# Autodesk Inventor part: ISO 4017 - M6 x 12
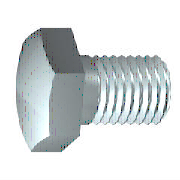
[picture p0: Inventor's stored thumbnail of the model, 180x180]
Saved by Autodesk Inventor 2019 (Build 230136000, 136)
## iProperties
Created: 2018-01
Part Number: ISO 4017 - M6 x 12
Material: Acier inoxydable 440C
Description: Vis à tête hexagonale
Document SubType Name: Modeling
Standard: ISO 4017
Designer: Thier
Standard Revision: Fourth edition 2011-04-01
Standards Organization: ISO
Language: fr-FR
Size Designation: M6 x 12
Categories: <MemberInstance><Categories><Category DisplayName="Visserie" InternalName="e4da775c-781d-43d5-af7c-5136215cf5a6" Mnemonic="FSTN"><Category DisplayName="Vis" Int
Density: 7.75 g/cm^3
Appearance: Semi-poli
IsCustomPart: 0
Author: Thier
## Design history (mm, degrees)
sketch "Esquisse1"
  geometry: L1 (0, 4.44)-(0, 3); L2 (3, 3)-(12, 3); L3 (12, 3)-(12, 0); L4 (12, 0)-(-0.5, 0); L5 (-3, 0)-(14.5, 0) reference; L6 (-0.5, 0)-(-0.5, 4.44); L7 (-0.5, 4.44)-(0, 4.44); L8 (3, 3)-(2.386, 3); L9 (2.386, 3)-(0, 3); L10 (0, -0.888)-(0, 5.328) reference
  constraints: 16 end point, 2 collinear, 2 perpendicular, 1 parallel
  dimensions: "d0" = 12 distance between parallel lines of L3 L1 (= NLG); "d1" = 9 distance from line of L2.start L3 (= GEL); "d2" = 6 diameter of L2 L4 (= GD); "d9" = 0.5001 distance between parallel lines of L6 L1 (computed from SD); "d10" = 8.88 diameter of L7 L4 (= SD2); "d13" = 0.61355 distance of L2.start L8.end (computed from GAL); "d14" = 6 diameter of L9 L4 (= BDM)
revolve "Corps" sketch "Esquisse1" stored, may be unused: angle "d12" = 90 deg
sketch "Esquisse2"
  geometry: L1 (0, 5.774)-(5, 2.887); L2 (5, 2.887)-(5, -2.887); L3 (5, -2.887)-(0, -5.774); L4 (0, -5.774)-(-5, -2.887); L5 (-5, -2.887)-(-5, 2.887); L6 (-5, 2.887)-(0, 5.774); 2 further points
  constraints: 12 end point, 1 coincident, 1 vertical, 11 other
  dimensions: "d11" = 10 distance between parallel lines of L5 L2 (= SW)
extrude "Tête" join sketch "Esquisse2" distance "d3" = 3.5 (= KOH - SD); taper "d4" = 0 deg
sketch "Esquisse4"
  geometry: L1 (-4, 5)-(-4, 5.774); L2 (-4, 5.774)-(-3.554, 5.774); L3 (-3.554, 5.774)-(-4, 5); L4 (-4.7, 0)-(0.2, 0) reference; L5 (-0.5, 5.774)-(-4, 5.774) reference; L6 (-4, 2.887)-(-4, 5.774) reference
  constraints: 6 end point, 2 collinear, 1 perpendicular, 1 vertical
  dimensions: "d5" = 30 deg angle of L3 L1 (= ANG1); "d19" = 10 diameter of L1.start L4 (= SW0)
revolve "Chanfrein1" sketch "Esquisse4" stored, may be unused: angle "d21" = 90 deg
workplane "Work Plane1"
body "Solid1"
feature "Filetage" dims "d15" = 9 (= GEL), "d16" = 0
chamfer "Chanfrein2" distance "d6" = 0.61345 (= -0.5 x SPD + 0.5 x GD); stored, may be unused: second distance "d7" = 0.61355 (computed from GUL), angle "d55" = 45 deg
other parameters: "NLG" = 12 [user parameter; used in 1 equation term], "GD" = 6 (= NND) [user parameter; used in 2 equation terms], "BDM" = 6 (= NND) [user parameter; used in 1 equation term], "KOH" = 4 [user parameter; used in 1 equation term], "GEL" = 9 [user parameter; used in 2 equation terms], "SW" = 10 [user parameter; used in 2 equation terms], "SW0" = 10 (= SW) [user parameter; used in 1 equation term], "SPD" = 4.7731 (= NND - 1.2269 x PTC) [user parameter; used in 1 equation term], "SD2" = 8.88 [user parameter; used in 2 equation terms], "SD" = 0.5 [user parameter; used in 2 equation terms], "ANG1" = 30 deg [user parameter; used in 1 equation term], "GAL" = 0.61345 (= 0.61345 x PTC) [user parameter; used in 1 equation term], "GUL" = 0.61345 (= 0.61345 x PTC) [user parameter; used in 1 equation term], "d8" = 0, "RR" = 0.25 [user parameter], "d57" = 0, "d58" = 0, "GD1" = 4.7731 (= THREADDIA - 1.2269 x PTC) [user parameter], "THREADDIA" = 6 [user parameter; used in 1 equation term], "SDH" = 8.88 (= SD2) [user parameter], "SDHG" = 3 [user parameter], "TOA" = 30 deg [user parameter], "PTC" = 1 [user parameter; used in 5 equation terms], "NND" = 6 [user parameter; used in 3 equation terms], "E0" = 11.55 [user parameter]
